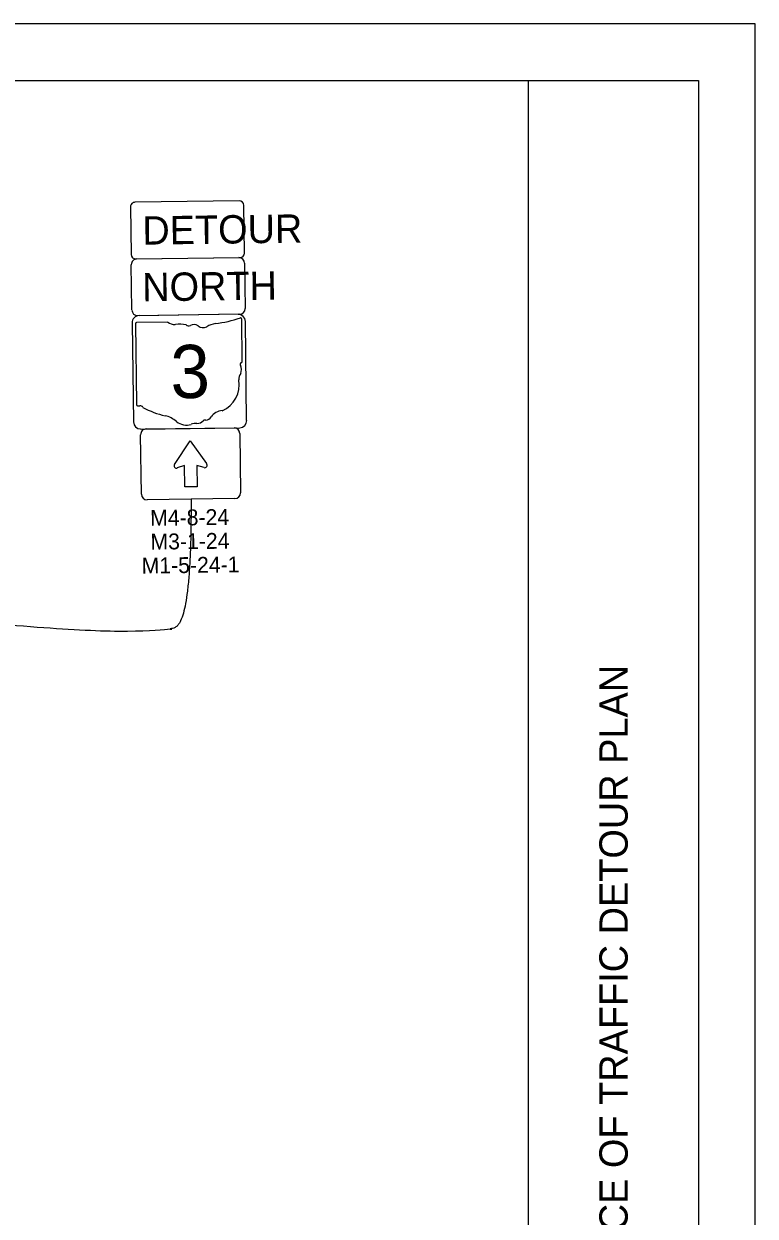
# Model space of a CAD drawing. Extents: x -15.3 to 34, y 0 to 22.
# Drawn here: x 27.55 to 34, y 11.48 to 22 of the extents above; entities that cross this region are included whole.
import ezdxf

# ---------------------------------------------------------------- set-up
doc = ezdxf.new("R2010")
doc.units = 0
for name, color, linetype in [('SC_Scratch1', 7, 'Continuous'), ('SH_Border', 7, 'Continuous'), ('SH_Cut_Line', 7, 'Continuous'), ('SH_Data', 7, 'Continuous'), ('SH_Text', 7, 'Continuous'), ('SN_P_Signs', 7, 'Continuous')]:
    doc.layers.add(name, color=color, linetype=linetype)

msp = doc.modelspace()

# ---------------------------------------------------------------- linework, layer by layer
at = {"layer": 'SH_Border'}
msp.add_line((32, 0.5), (32, 21.5), dxfattribs=at)
msp.add_lwpolyline([(1.5, 21.5), (33.5, 21.5), (33.5, 0.5), (1.5, 0.5)], close=True, dxfattribs=at)
at = {"layer": 'SH_Cut_Line'}
msp.add_lwpolyline([(0, 0), (34, 0), (34, 22), (0, 22)], close=True, dxfattribs=at)
at = {"layer": 'SH_Text'}
msp.add_open_spline([(29.021, 17.807), (29.026, 16.783), (28.756, 16.582), (25.512, 16.854), (24.827, 16.364), (24.556, 16.333), (24.565, 16.497)], degree=2, dxfattribs=at)
at = {"layer": 'SN_P_Signs'}
for p, q in [((28.543, 19.926), (29.443, 19.938)), ((29.494, 19.889), (29.499, 19.489)), ((28.499, 19.476), (28.494, 19.876)), ((28.531, 19.354), (28.541, 18.642)), ((28.815, 19.37), (28.541, 19.366)), ((29.45, 19.438), (28.55, 19.426)), ((29.473, 19.024), (29.468, 19.396)), ((29.473, 19.024), (29.473, 19.024)), ((28.626, 18.427), (29.401, 18.437)), ((28.583, 17.852), (28.576, 18.376)), ((28.875, 18.114), (29.014, 18.323)), ((29.014, 18.323), (29.157, 18.121)), ((29.451, 18.388), (29.458, 17.863)), ((28.963, 18.103), (28.899, 18.083)), ((28.965, 17.916), (28.963, 18.103)), ((29.136, 18.086), (29.072, 18.105)), ((29.072, 18.105), (29.074, 17.917)), ((29.074, 17.917), (28.965, 17.916)), ((29.409, 17.812), (28.634, 17.802))]:
    msp.add_line(p, q, dxfattribs=at)
for points in [[(29.447, 20.438), (28.527, 20.426)], [(28.487, 20.385), (28.493, 19.966)], [(29.493, 19.979), (29.487, 20.399)], [(28.533, 19.926), (29.453, 19.938)], [(28.501, 19.363), (28.512, 18.488)], [(29.437, 19.438), (28.562, 19.426)], [(29.512, 18.501), (29.501, 19.376)], [(28.576, 18.426), (29.451, 18.438)]]:
    msp.add_lwpolyline(points, dxfattribs=at)
for centre, radius, start, end in [((28.527, 20.386), 0.04, 90.7508, 180.7508), ((29.447, 20.398), 0.04, 0.7508, 90.7508), ((28.533, 19.966), 0.04, 180.7508, 270.7508), ((28.544, 19.876), 0.05, 90.7508, 180.7508), ((29.444, 19.888), 0.05, 0.7508, 90.7508), ((29.453, 19.978), 0.04, 270.7508, 0.7508), ((28.549, 19.476), 0.05, 180.7508, 270.7508), ((29.449, 19.488), 0.05, 270.7508, 0.7508), ((28.563, 19.364), 0.0625, 90.7508, 180.7508), ((28.542, 19.356), 0.0109, 98.8809, 188.8809), ((28.879, 19.453), 0.105, 232.3703, 271.8627), ((29.264, 19.158), 0.2, 98.097, 121.5197), ((29.122, 20.344), 0.994, 276.5953, 289.6573), ((29.438, 19.375), 0.0625, 0.7508, 90.7508), ((29.458, 19.397), 0.0104, 352.6129, 98.4888), ((28.921, 18.972), 0.378, 81.2375, 95.7391), ((29.001, 19.365), 0.0304, 220.5429, 297.8532), ((29.047, 19.284), 0.0632, 55.2175, 119.8919), ((29.127, 19.397), 0.076, 234.607, 295.579), ((29.471, 18.997), 0.0162, 108.6948, 211.0878), ((29.369, 18.948), 0.097, 340.7838, 24.4004), ((29.462, 19.022), 0.0112, 290.3546, 8.4849), ((29.198, 18.817), 0.249, 293.0597, 9.7366), ((29.513, 18.869), 0.0705, 137.5573, 187.6804), ((28.552, 18.641), 0.011, 172.7092, 259.0574), ((28.552, 18.714), 0.0836, 268.0898, 281.3547), ((28.571, 18.602), 0.0302, 30.4992, 94.0225), ((28.943, 19.246), 0.718, 241.1637, 257.9493), ((28.741, 18.325), 0.225, 47.935, 76.5868), ((29.133, 18.581), 0.0803, 283.624, 324.0279), ((29.307, 18.453), 0.136, 95.1539, 143.3276), ((28.575, 18.489), 0.0625, 180.7508, 270.7508), ((28.626, 18.377), 0.05, 90.7508, 180.7508), ((28.981, 18.604), 0.143, 231.4512, 287.0426), ((29.066, 18.359), 0.117, 86.4459, 111.9607), ((29.074, 18.552), 0.0759, 269.5278, 316.3001), ((29.144, 18.484), 0.0214, 66.5025, 133.3992), ((29.401, 18.387), 0.05, 0.7508, 90.7508), ((29.45, 18.5), 0.0625, 270.7508, 0.7508), ((28.892, 18.102), 0.0209, 146.162, 287.9554), ((29.142, 18.106), 0.0209, 253.5462, 45.7604), ((28.633, 17.852), 0.05, 180.7508, 270.7508), ((29.408, 17.862), 0.05, 270.7508, 0.7508)]:
    msp.add_arc(centre, radius, start, end, dxfattribs=at)

# ---------------------------------------------------------------- texts
at = {"layer": 'SC_Scratch1'}
for s, p in [('M4-8-24', (28.661, 17.572)), ('M3-1-24', (28.664, 17.362)), ('M1-5-24-1', (28.586, 17.151))]:
    msp.add_text(s, height=0.14, rotation=0.7508, dxfattribs=at).set_placement(p)
at = {"layer": 'SH_Data'}
msp.add_text('MAINTENANCE OF TRAFFIC DETOUR PLAN', height=0.25, rotation=90, dxfattribs=at).set_placement((32.875, 9.381))
at = {"layer": 'SN_P_Signs'}
for s, height, p in [('DETOUR', 0.25, (28.593, 20.052)), ('NORTH', 0.25, (28.592, 19.552)), ('3', 0.469, (28.842, 18.697))]:
    msp.add_text(s, height=height, rotation=0.7508, dxfattribs=at).set_placement(p)

doc.saveas('drawing.dxf')
